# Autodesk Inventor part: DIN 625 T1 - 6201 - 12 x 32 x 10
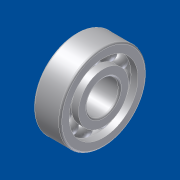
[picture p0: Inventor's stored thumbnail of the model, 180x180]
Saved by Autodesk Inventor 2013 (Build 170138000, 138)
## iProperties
Created: 2002-06
Part Number: DIN 625 T1 - 6201 - 12 x 32 x 10
Material: Standard
Catalog Web Link: file:///D:/Programme/Inventor%205.3/Content/Din/index.htm?doNavigateId=4AD379DC-10FA-4853-8ADA-6A4A7C43E350|722B2627B16B11D4BA6900C04F798F98|true
Description: Rillenkugellager
Document SubType Name: Standard Catalog Part
Standard: DIN 625 T1 - 6201 - 12 x 32 x 10
Designer: dl
Density: 1 g/cm^3
Control State: 0
Master: False
Checked Out: False
Shininess: 20.0
Length Units: 11269
Angle Units: 11279
Time Units: 11290
Mass Units: 11283
Length Display Precision: 3
Angle Display Precision: 2
Compacted: True
KLASSIFIKATION: 31171504
HERSTELLER: DIN Normsystem
Density: 0.0
Volumn: 0.0
Area: 0.0
PropertySet Name: Model Information
Author: dl
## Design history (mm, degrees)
feature "Basis1"
body "Solid1"
